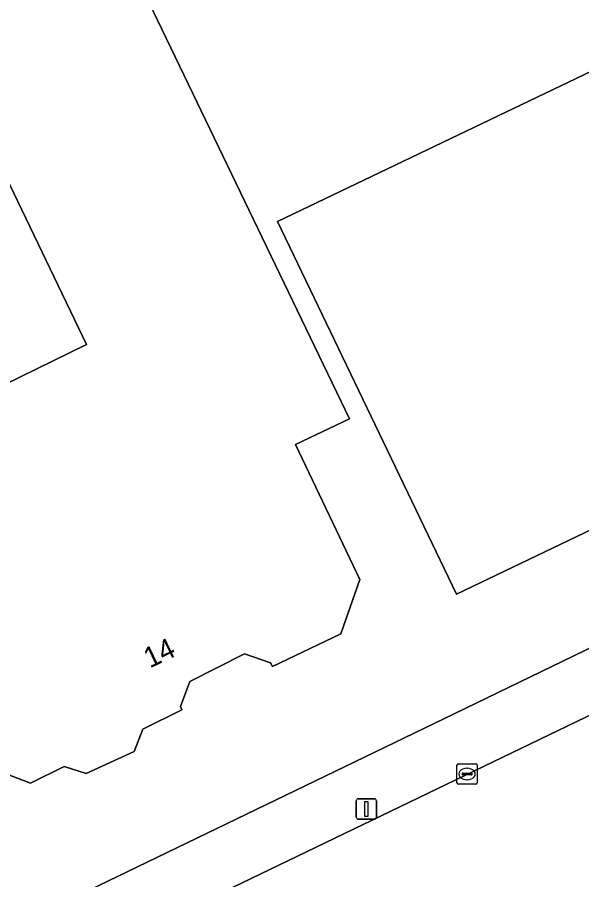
# Model space of a CAD drawing. Extents: x 157692 to 159674, y 381452 to 383291.
# Drawn here: x 158074.32 to 158101.97, y 381676.57 to 381718.82 of the extents above; entities that cross this region are included whole.
import ezdxf

# ---------------------------------------------------------------- set-up
doc = ezdxf.new("R2010")
doc.units = 0
for name, color, linetype in [('IMGEO_Erf', 7, 'Continuous'), ('IMGEO_Kolk', 7, 'Continuous'), ('IMGEO_Lichtmast', 7, 'Continuous'), ('IMGEO_Pand', 7, 'Continuous'), ('IMGEO_Pand_nummerreeks', 7, 'Continuous'), ('IMGEO_Rijbaan_lokaal_gesloten', 7, 'Continuous'), ('IMGEO_Voetpad_open', 7, 'Continuous')]:
    doc.layers.add(name, color=color, linetype=linetype)

msp = doc.modelspace()

# ---------------------------------------------------------------- linework, layer by layer
at = {"layer": 'IMGEO_Erf'}
for points in [[(158006.881, 381609.083), (158005.905, 381627.867), (158005.466, 381636.382), (158005.223, 381641.106), (158032.78, 381654.365), (158038.282, 381657.004), (158060.573, 381667.757), (158067.21, 381670.951), (158069.612, 381672.132), (158075.377, 381674.875), (158095.213, 381684.451), (158107.373, 381690.341), (158121.318, 381697.1), (158122.884, 381701.311), (158109.399, 381729.267), (158106.88, 381734.578), (158102.545, 381743.606), (158102.331, 381744.049), (158099.751, 381749.471), (158099.496, 381750), (158086.302, 381777.417), (158083.311, 381783.632), (158080.659, 381789.142)], [(158070.933, 381728.483), (158075.432, 381730.662), (158090.593, 381699.145), (158087.956, 381697.889), (158091.103, 381691.273), (158090.172, 381688.615), (158086.823, 381687.022), (158086.722, 381687.201), (158085.446, 381687.641), (158082.781, 381686.285), (158082.315, 381685.049), (158082.39, 381684.9), (158080.468, 381683.952), (158080.056, 381682.847), (158077.694, 381681.766), (158076.614, 381682.114), (158074.971, 381681.307), (158072.255, 381682.327)], [(158067.138, 381697.606), (158077.722, 381702.786), (158066.42, 381726.297)]]:
    msp.add_lwpolyline(points, dxfattribs=at)
msp.add_lwpolyline([(158107.496, 381718.594), (158114.941, 381703.211), (158117.435, 381700.917), (158095.837, 381690.555), (158087.076, 381708.818)], close=True, dxfattribs=at)
at = {"layer": 'IMGEO_Kolk'}
for p, q in [((158095.854, 381681.323), (158095.854, 381682.175)), ((158095.929, 381682.249), (158096.781, 381682.249)), ((158096.342, 381682.029), (158096.367, 381682.029)), ((158096.855, 381682.175), (158096.855, 381681.323)), ((158096.113, 381681.743), (158096.113, 381681.755)), ((158096.551, 381681.706), (158096.153, 381681.706)), ((158096.156, 381681.792), (158096.554, 381681.792)), ((158096.597, 381681.755), (158096.597, 381681.743)), ((158096.781, 381681.249), (158095.929, 381681.249)), ((158096.365, 381681.469), (158096.34, 381681.469))]:
    msp.add_line(p, q, dxfattribs=at)
for points in [[(158095.854, 381681.323), (158095.854, 381682.175)], [(158095.929, 381682.249), (158096.781, 381682.249)], [(158096.855, 381682.175), (158096.855, 381681.323)], [(158096.781, 381681.249), (158095.929, 381681.249)]]:
    msp.add_lwpolyline(points, dxfattribs=at)
for centre, radius, start, end in [((158095.931, 381682.173), 0.0765, 91.552, 178.448), ((158095.931, 381682.173), 0.0765, 91.552, 178.448), ((158096.779, 381682.173), 0.0765, 1.552, 88.448), ((158096.779, 381682.173), 0.0765, 1.552, 88.448), ((158096.153, 381681.752), 0.0403, 85.8775, 175.7526), ((158096.15, 381681.742), 0.0366, 178.938, 274.7102), ((158096.554, 381681.749), 0.043, 264.8664, 352.4533), ((158096.558, 381681.754), 0.0386, 1.7309, 96.639), ((158095.931, 381681.325), 0.0765, 181.552, 268.448), ((158095.931, 381681.325), 0.0765, 181.552, 268.448), ((158096.779, 381681.325), 0.0765, 271.552, 358.448), ((158096.779, 381681.325), 0.0765, 271.552, 358.448)]:
    msp.add_arc(centre, radius, start, end, dxfattribs=at)
for centre, major_axis, ratio, start_param, end_param in [((158096.341, 381681.749), (-0.387, 0.002), 0.722429, 4.712389, 7.853982), ((158096.366, 381681.749), (-0.39, 0.002), 0.717154, 1.570796, 4.712389)]:
    msp.add_ellipse(centre, major_axis=major_axis, ratio=ratio, start_param=start_param, end_param=end_param, dxfattribs=at)
at = {"layer": 'IMGEO_Lichtmast'}
for p, q in [((158090.926, 381679.635), (158090.926, 381680.435)), ((158090.926, 381680.435), (158090.926, 381679.635)), ((158091.026, 381680.535), (158091.816, 381680.535)), ((158091.816, 381680.535), (158091.026, 381680.535)), ((158091.916, 381680.435), (158091.916, 381679.635)), ((158091.916, 381679.635), (158091.916, 381680.435)), ((158091.816, 381679.535), (158091.026, 381679.535)), ((158091.026, 381679.535), (158091.816, 381679.535))]:
    msp.add_line(p, q, dxfattribs=at)
msp.add_lwpolyline([(158091.346, 381680.41), (158091.496, 381680.41), (158091.496, 381679.66), (158091.346, 381679.66), (158091.346, 381680.41)], dxfattribs=at)
for centre, start, end in [((158091.026, 381680.435), 90, 180), ((158091.026, 381680.435), 90, 180), ((158091.816, 381680.435), 0, 90), ((158091.816, 381680.435), 360, 90), ((158091.026, 381679.635), 180, 270), ((158091.026, 381679.635), 180, 270), ((158091.816, 381679.635), 270, 0), ((158091.816, 381679.635), 270, 0)]:
    msp.add_arc(centre, 0.1, start, end, dxfattribs=at)
at = {"layer": 'IMGEO_Pand'}
for points in [[(158072.255, 381682.327), (158074.971, 381681.307), (158076.614, 381682.114), (158077.694, 381681.766), (158080.056, 381682.847), (158080.468, 381683.952), (158082.39, 381684.9), (158082.315, 381685.049), (158082.781, 381686.285), (158085.446, 381687.641), (158086.722, 381687.201), (158086.823, 381687.022), (158090.172, 381688.615), (158091.103, 381691.273), (158087.956, 381697.889), (158090.593, 381699.145), (158075.432, 381730.662), (158070.933, 381728.483)], [(158066.42, 381726.297), (158077.722, 381702.786), (158067.138, 381697.606)]]:
    msp.add_lwpolyline(points, dxfattribs=at)
msp.add_lwpolyline([(158095.837, 381690.555), (158117.435, 381700.917), (158114.941, 381703.211), (158107.496, 381718.594), (158087.076, 381708.818)], close=True, dxfattribs=at)
at = {"layer": 'IMGEO_Rijbaan_lokaal_gesloten'}
msp.add_lwpolyline([(158122.546, 381694.375), (158120.418, 381693.339), (158076.639, 381672.23), (158070.922, 381669.494), (158068.454, 381668.331), (158061.817, 381665.104), (158039.529, 381654.389), (158034.067, 381651.688), (158020.546, 381645.249)], dxfattribs=at)
at = {"layer": 'IMGEO_Voetpad_open'}
msp.add_lwpolyline([(158125.681, 381697.64), (158122.884, 381701.311), (158121.318, 381697.1), (158107.373, 381690.341), (158095.213, 381684.451), (158075.377, 381674.875), (158076.639, 381672.23), (158120.418, 381693.339)], dxfattribs=at)

# ---------------------------------------------------------------- texts
at = {"layer": 'IMGEO_Pand_nummerreeks'}
msp.add_text('14', height=1, rotation=25.6763, dxfattribs=at).set_placement((158080.817, 381686.914))

doc.saveas('drawing.dxf')
